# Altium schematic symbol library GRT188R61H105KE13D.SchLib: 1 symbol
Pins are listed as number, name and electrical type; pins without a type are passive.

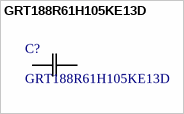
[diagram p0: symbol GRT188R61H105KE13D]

## GRT188R61H105KE13D
designator C?
Description; Manufacturer_Name: Murata
footprint CAP_GRT188R61H105KE13D_MUR
pins: 1, 2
